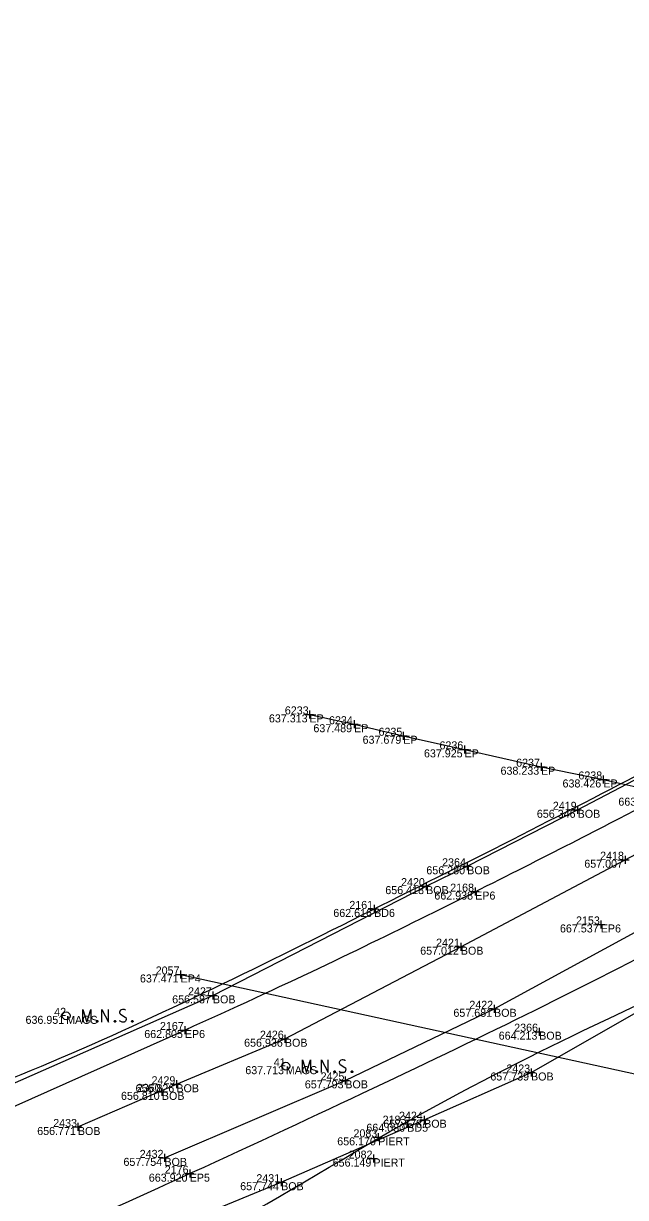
# Model space of a CAD drawing. Extents: x 2197382 to 2204062, y 634117 to 636522.
# Drawn here: x 2202463 to 2202538.2, y 635231.8 to 635378.5 of the extents above; entities that cross this region are included whole.
import ezdxf

# ---------------------------------------------------------------- set-up
doc = ezdxf.new("R2010")
doc.units = 0
for name, color, linetype in [('_CIVIL_CONSTRUCTION', 7, 'Continuous'), ('BR_X_SV_Bottom_of_Beam', 7, 'Continuous'), ('BR_X_SV_Bottom_of_Beam_Text', 7, 'Continuous'), ('BR_X_SV_Deck_Top', 7, 'Continuous'), ('BR_X_SV_Deck_Top_Text', 7, 'Continuous'), ('BR_X_SV_Pier_Cap_Top_Text', 7, 'Continuous'), ('GE_P_Alignment_100_Distances', 7, 'Continuous'), ('SH_Border', 7, 'Continuous'), ('SH_Cut_Line', 7, 'Continuous'), ('SH_Data', 7, 'Continuous'), ('SV_P_Control_Cells_Set', 7, 'Continuous')]:
    doc.layers.add(name, color=color, linetype=linetype)

msp = doc.modelspace()

# ---------------------------------------------------------------- linework, layer by layer
at = {"layer": '_CIVIL_CONSTRUCTION'}
for p, q in [((2202498.24, 635292.2), (2202499.24, 635292.2)), ((2202498.74, 635292.7), (2202498.74, 635291.7)), ((2202498.74, 635292.2), (2202498.74, 635292.2)), ((2202503.82, 635290.97), (2202504.82, 635290.97)), ((2202504.32, 635291.47), (2202504.32, 635290.47)), ((2202504.32, 635290.97), (2202504.32, 635290.97)), ((2202509.96, 635289.53), (2202510.96, 635289.53)), ((2202510.46, 635290.03), (2202510.46, 635289.03)), ((2202510.46, 635289.53), (2202510.46, 635289.53)), ((2202517.62, 635287.83), (2202518.62, 635287.83)), ((2202518.12, 635288.33), (2202518.12, 635287.33)), ((2202518.12, 635287.83), (2202518.12, 635287.83)), ((2202527.18, 635285.66), (2202528.18, 635285.66)), ((2202527.68, 635286.16), (2202527.68, 635285.16)), ((2202527.68, 635285.66), (2202527.68, 635285.66)), ((2202534.97, 635284.07), (2202535.97, 635284.07)), ((2202535.47, 635284.57), (2202535.47, 635283.57)), ((2202535.47, 635284.07), (2202535.47, 635284.07)), ((2202532.26, 635280.78), (2202532.26, 635279.78)), ((2202531.76, 635280.28), (2202532.76, 635280.28)), ((2202532.26, 635280.28), (2202532.26, 635280.28)), ((2202538.19, 635274.54), (2202538.19, 635273.54)), ((2202517.96, 635273.22), (2202518.96, 635273.22)), ((2202518.46, 635273.72), (2202518.46, 635272.72)), ((2202518.46, 635273.22), (2202518.46, 635273.22)), ((2202537.69, 635274.04), (2202538.69, 635274.04)), ((2202538.19, 635274.04), (2202538.19, 635274.04)), ((2202512.82, 635270.74), (2202513.82, 635270.74)), ((2202513.32, 635271.24), (2202513.32, 635270.24)), ((2202513.32, 635270.74), (2202513.32, 635270.74)), ((2202519.45, 635270.55), (2202519.45, 635269.55)), ((2202518.95, 635270.05), (2202519.95, 635270.05)), ((2202519.45, 635270.05), (2202519.45, 635270.05)), ((2202506.32, 635267.89), (2202507.32, 635267.89)), ((2202506.82, 635268.39), (2202506.82, 635267.39)), ((2202506.82, 635267.89), (2202506.82, 635267.89)), ((2202534.65, 635265.95), (2202535.65, 635265.95)), ((2202535.15, 635266.45), (2202535.15, 635265.45)), ((2202535.15, 635265.95), (2202535.15, 635265.95)), ((2202517.16, 635263.17), (2202518.16, 635263.17)), ((2202517.66, 635263.67), (2202517.66, 635262.67)), ((2202517.66, 635263.17), (2202517.66, 635263.17)), ((2202482.63, 635260.2), (2202482.63, 635259.2)), ((2202482.13, 635259.7), (2202483.13, 635259.7)), ((2202482.63, 635259.7), (2202482.63, 635259.7)), ((2202486.17, 635257.09), (2202487.17, 635257.09)), ((2202486.67, 635257.59), (2202486.67, 635256.59)), ((2202486.67, 635257.09), (2202486.67, 635257.09)), ((2202521.81, 635255.91), (2202521.81, 635254.91)), ((2202521.31, 635255.41), (2202522.31, 635255.41)), ((2202521.81, 635255.41), (2202521.81, 635255.41)), ((2202482.66, 635252.76), (2202483.66, 635252.76)), ((2202483.16, 635253.26), (2202483.16, 635252.26)), ((2202483.16, 635252.76), (2202483.16, 635252.76)), ((2202526.95, 635252.55), (2202527.95, 635252.55)), ((2202527.45, 635253.05), (2202527.45, 635252.05)), ((2202527.45, 635252.55), (2202527.45, 635252.55)), ((2202495.17, 635251.67), (2202496.17, 635251.67)), ((2202495.67, 635252.17), (2202495.67, 635251.17)), ((2202495.67, 635251.67), (2202495.67, 635251.67)), ((2202503.22, 635246.97), (2202503.22, 635245.97)), ((2202525.93, 635247.45), (2202526.93, 635247.45)), ((2202526.43, 635247.95), (2202526.43, 635246.95)), ((2202526.43, 635247.45), (2202526.43, 635247.45)), ((2202480.29, 635245.53), (2202480.29, 635244.53)), ((2202481.61, 635245.98), (2202482.61, 635245.98)), ((2202482.11, 635246.48), (2202482.11, 635245.48)), ((2202482.11, 635245.98), (2202482.11, 635245.98)), ((2202502.72, 635246.47), (2202503.72, 635246.47)), ((2202503.22, 635246.47), (2202503.22, 635246.47)), ((2202479.79, 635245.03), (2202480.79, 635245.03)), ((2202480.29, 635245.03), (2202480.29, 635245.03)), ((2202469.79, 635241.14), (2202469.79, 635240.14)), ((2202510.46, 635241.05), (2202511.46, 635241.05)), ((2202510.96, 635241.55), (2202510.96, 635240.55)), ((2202510.96, 635241.05), (2202510.96, 635241.05)), ((2202512.57, 635241.55), (2202513.57, 635241.55)), ((2202513.07, 635242.05), (2202513.07, 635241.05)), ((2202513.07, 635241.55), (2202513.07, 635241.55)), ((2202469.29, 635240.64), (2202470.29, 635240.64)), ((2202469.79, 635240.64), (2202469.79, 635240.64)), ((2202506.83, 635239.35), (2202507.83, 635239.35)), ((2202507.33, 635239.85), (2202507.33, 635238.85)), ((2202507.33, 635239.35), (2202507.33, 635239.35)), ((2202480.11, 635236.78), (2202481.11, 635236.78)), ((2202480.61, 635237.28), (2202480.61, 635236.28)), ((2202480.61, 635236.78), (2202480.61, 635236.78)), ((2202506.23, 635236.69), (2202507.23, 635236.69)), ((2202506.73, 635237.19), (2202506.73, 635236.19)), ((2202506.73, 635236.69), (2202506.73, 635236.69)), ((2202483.77, 635235.31), (2202483.77, 635234.31)), ((2202483.27, 635234.81), (2202484.27, 635234.81)), ((2202483.77, 635234.81), (2202483.77, 635234.81)), ((2202494.7, 635233.74), (2202495.7, 635233.74)), ((2202495.2, 635234.24), (2202495.2, 635233.24)), ((2202495.2, 635233.74), (2202495.2, 635233.74))]:
    msp.add_line(p, q, dxfattribs=at)
at = {"layer": 'BR_X_SV_Bottom_of_Beam'}
msp.add_line((2202471.48, 635223.99), (2202495.2, 635233.74), dxfattribs=at)
for points in [[(2202513.32, 635270.74), (2202518.46, 635273.22), (2202532.26, 635280.28), (2202548.24, 635288.65), (2202560.65, 635295.12), (2202588.28, 635310.4), (2202608.69, 635322.99), (2202620.52, 635330.21), (2202626.07, 635333.71), (2202636.25, 635340.13), (2202656.93, 635353.89), (2202662.46, 635358.97), (2202720.9, 635399.77), (2202735.15, 635410.44), (2202760.7, 635432.08)], [(2202480.61, 635236.78), (2202503.22, 635246.47), (2202521.81, 635255.41), (2202544.65, 635267.81), (2202563.46, 635278.16), (2202584.32, 635289.66), (2202600.02, 635298.57)], [(2202469.79, 635240.64), (2202482.11, 635245.98), (2202495.67, 635251.67), (2202517.66, 635263.17), (2202538.19, 635274.04), (2202552.84, 635281.79), (2202572.87, 635292.54)], [(2202452.05, 635241.83), (2202486.67, 635257.09), (2202513.32, 635270.74)], [(2202495.2, 635233.74), (2202513.07, 635241.55), (2202526.43, 635247.45), (2202550.74, 635261.3)]]:
    msp.add_lwpolyline(points, dxfattribs=at)
at = {"layer": 'BR_X_SV_Deck_Top'}
for points in [[(2202430.05, 635233.59), (2202439.74, 635238.51), (2202466.34, 635247.69), (2202507.17, 635268.03), (2202543.72, 635286.4), (2202574.88, 635303.71), (2202604.91, 635320.16), (2202634.13, 635339.4), (2202663.02, 635358.59), (2202692.44, 635376.51), (2202729.25, 635404.45), (2202755.81, 635426.42), (2202769.74, 635438.84)], [(2202458.05, 635216.68), (2202477.12, 635219.98), (2202511.72, 635243.78), (2202554.96, 635262.3), (2202588.01, 635280.67), (2202608.34, 635292.39), (2202640.83, 635312.14), (2202668.15, 635329.95), (2202698.57, 635351.31), (2202722.13, 635368.65), (2202754.6, 635393.43), (2202777.49, 635412.29), (2202789.61, 635422.64)]]:
    msp.add_open_spline(points, degree=3, dxfattribs=at)
at = {"layer": 'GE_P_Alignment_100_Distances'}
for p, q in [((2202535.15, 635265.95), (2202535.15, 635265.95)), ((2202437.86, 635232.53), (2202483.16, 635252.76))]:
    msp.add_line(p, q, dxfattribs=at)
for points in [[(2202498.74, 635292.2), (2202504.32, 635290.97), (2202510.46, 635289.53), (2202518.12, 635287.83), (2202527.68, 635285.66), (2202535.47, 635284.07), (2202543.69, 635282.23), (2202552.96, 635280.17), (2202564.04, 635277.92), (2202577.1, 635275.33), (2202589.15, 635272.89), (2202599.87, 635270.95), (2202613.44, 635268.28), (2202628.15, 635265.39), (2202641.92, 635262.82), (2202654.4, 635260.66), (2202664.33, 635258.84), (2202676.16, 635256.72), (2202690.38, 635253.86), (2202704.42, 635251.17), (2202718.67, 635248.71), (2202737.35, 635245.36), (2202761.23, 635240.85), (2202781.34, 635237.18)], [(2202482.63, 635259.7), (2202569.32, 635240.74), (2202617.18, 635230.71), (2202631.86, 635227.59), (2202654.83, 635223.14), (2202694.02, 635215.69), (2202726.45, 635210.27), (2202846.08, 635190.3)]]:
    msp.add_lwpolyline(points, dxfattribs=at)
for points in [[(2202483.16, 635252.76), (2202495.4, 635258.23), (2202515.21, 635267.82), (2202539.51, 635280.18), (2202556.27, 635289.07), (2202570.79, 635297.09), (2202585.76, 635305.34), (2202607.83, 635319.01), (2202630.78, 635332.65), (2202656.43, 635348.81), (2202675.69, 635362.47), (2202698.98, 635379.18), (2202729.9, 635401.35), (2202753.67, 635420.87), (2202767.82, 635433.18)], [(2202457.67, 635223.28), (2202466.48, 635226.87), (2202500.46, 635242.35), (2202539.48, 635261.18), (2202573.06, 635279.52), (2202585.61, 635286.63), (2202599.84, 635294.84), (2202617.62, 635305.23), (2202642.29, 635320.4), (2202667.37, 635336.77), (2202691.72, 635353.63), (2202713.41, 635369.4), (2202739.64, 635388.97), (2202758.66, 635404.28), (2202770.06, 635413.81)]]:
    msp.add_open_spline(points, degree=3, dxfattribs=at)
at = {"layer": 'SV_P_Control_Cells_Set'}
for points in [[(2202470.42, 635253.73), (2202470.42, 635255.33), (2202470.92, 635253.73), (2202471.41, 635255.33), (2202471.41, 635253.73)], [(2202472.79, 635253.73), (2202472.79, 635255.33), (2202473.61, 635253.73), (2202473.61, 635255.33)], [(2202475.76, 635255.22), (2202475.74, 635255.24), (2202475.71, 635255.27), (2202475.61, 635255.31), (2202475.49, 635255.33), (2202475.4, 635255.33), (2202475.37, 635255.33), (2202475.22, 635255.29), (2202475.1, 635255.22), (2202475.02, 635255.12), (2202475, 635255.02), (2202475, 635254.94), (2202475.02, 635254.84), (2202475.11, 635254.75), (2202475.72, 635254.37), (2202475.77, 635254.32), (2202475.8, 635254.27), (2202475.82, 635254.2), (2202475.82, 635254.12), (2202475.81, 635254.05), (2202475.8, 635254), (2202475.77, 635253.93), (2202475.75, 635253.88), (2202475.73, 635253.85), (2202475.7, 635253.81), (2202475.66, 635253.78), (2202475.62, 635253.76), (2202475.59, 635253.75), (2202475.49, 635253.73), (2202475.33, 635253.73), (2202475.23, 635253.76), (2202475.09, 635253.85), (2202475, 635253.92)], [(2202472.18, 635253.95), (2202472.24, 635253.95), (2202472.27, 635253.92), (2202472.3, 635253.87), (2202472.3, 635253.81), (2202472.27, 635253.76), (2202472.24, 635253.73), (2202472.18, 635253.73), (2202472.15, 635253.76), (2202472.12, 635253.81), (2202472.12, 635253.87), (2202472.15, 635253.92), (2202472.18, 635253.95)], [(2202474.4, 635253.95), (2202474.45, 635253.95), (2202474.48, 635253.92), (2202474.52, 635253.87), (2202474.52, 635253.81), (2202474.48, 635253.76), (2202474.45, 635253.73), (2202474.4, 635253.73), (2202474.36, 635253.76), (2202474.33, 635253.81), (2202474.33, 635253.87), (2202474.36, 635253.92), (2202474.4, 635253.95)], [(2202476.58, 635253.95), (2202476.63, 635253.95), (2202476.67, 635253.92), (2202476.7, 635253.87), (2202476.7, 635253.81), (2202476.67, 635253.76), (2202476.63, 635253.73), (2202476.58, 635253.73), (2202476.55, 635253.76), (2202476.51, 635253.81), (2202476.51, 635253.87), (2202476.55, 635253.92), (2202476.58, 635253.95)], [(2202497.87, 635247.44), (2202497.87, 635249.04), (2202498.38, 635247.44), (2202498.86, 635249.04), (2202498.86, 635247.44)], [(2202500.24, 635247.44), (2202500.24, 635249.04), (2202501.07, 635247.44), (2202501.07, 635249.04)], [(2202503.22, 635248.92), (2202503.2, 635248.95), (2202503.16, 635248.97), (2202503.06, 635249.01), (2202502.94, 635249.04), (2202502.85, 635249.04), (2202502.82, 635249.04), (2202502.68, 635249), (2202502.56, 635248.92), (2202502.48, 635248.82), (2202502.46, 635248.72), (2202502.46, 635248.65), (2202502.48, 635248.55), (2202502.57, 635248.46), (2202503.17, 635248.08), (2202503.23, 635248.03), (2202503.25, 635247.98), (2202503.27, 635247.9), (2202503.27, 635247.83), (2202503.26, 635247.75), (2202503.25, 635247.7), (2202503.23, 635247.64), (2202503.21, 635247.59), (2202503.19, 635247.55), (2202503.15, 635247.51), (2202503.12, 635247.49), (2202503.08, 635247.46), (2202503.04, 635247.45), (2202502.94, 635247.44), (2202502.79, 635247.44), (2202502.69, 635247.46), (2202502.55, 635247.55), (2202502.46, 635247.63)], [(2202499.64, 635247.65), (2202499.69, 635247.65), (2202499.72, 635247.63), (2202499.76, 635247.58), (2202499.76, 635247.51), (2202499.72, 635247.46), (2202499.69, 635247.44), (2202499.64, 635247.44), (2202499.6, 635247.46), (2202499.57, 635247.51), (2202499.57, 635247.58), (2202499.6, 635247.63), (2202499.64, 635247.65)], [(2202501.85, 635247.65), (2202501.91, 635247.65), (2202501.94, 635247.63), (2202501.97, 635247.58), (2202501.97, 635247.51), (2202501.94, 635247.46), (2202501.91, 635247.44), (2202501.85, 635247.44), (2202501.82, 635247.46), (2202501.79, 635247.51), (2202501.79, 635247.58), (2202501.82, 635247.63), (2202501.85, 635247.65)], [(2202504.03, 635247.65), (2202504.09, 635247.65), (2202504.12, 635247.63), (2202504.16, 635247.58), (2202504.16, 635247.51), (2202504.12, 635247.46), (2202504.09, 635247.44), (2202504.03, 635247.44), (2202504, 635247.46), (2202503.97, 635247.51), (2202503.97, 635247.58), (2202504, 635247.63), (2202504.03, 635247.65)]]:
    msp.add_lwpolyline(points, dxfattribs=at)
for centre in [(2202468.33, 635254.53), (2202495.78, 635248.24)]:
    msp.add_circle(centre, 0.497, dxfattribs=at)

# ---------------------------------------------------------------- texts
at = {"layer": 'BR_X_SV_Bottom_of_Beam_Text'}
for s, p in [('2419', (2202529.16, 635280.28)), ('656.346', (2202527.16, 635279.28)), ('BOB', (2202532.26, 635279.28)), ('2418', (2202535.07, 635274.04)), ('656.280', (2202513.35, 635272.22)), ('2364', (2202515.32, 635273.22)), ('BOB', (2202518.46, 635272.22)), ('657.007', (2202533.09, 635273.04)), ('2420', (2202510.19, 635270.74)), ('656.418', (2202508.22, 635269.74)), ('BOB', (2202513.32, 635269.74)), ('657.012', (2202512.58, 635262.17)), ('2421', (2202514.56, 635263.17)), ('BOB', (2202517.66, 635262.17)), ('656.587', (2202481.58, 635256.09)), ('2427', (2202483.56, 635257.09)), ('BOB', (2202486.67, 635256.09)), ('2422', (2202518.72, 635255.41)), ('657.681', (2202516.73, 635254.41)), ('BOB', (2202521.81, 635254.41)), ('2426', (2202492.55, 635251.67)), ('664.213', (2202522.39, 635251.55)), ('2366', (2202524.33, 635252.55)), ('BOB', (2202527.45, 635251.55)), ('656.936', (2202490.57, 635250.67)), ('BOB', (2202495.67, 635250.67)), ('2423', (2202523.35, 635247.45)), ('2429', (2202479, 635245.98)), ('2425', (2202500.13, 635246.47)), ('657.739', (2202521.35, 635246.45)), ('BOB', (2202526.43, 635246.45)), ('656.826', (2202477, 635244.98)), ('2360', (2202477.16, 635245.03)), ('BOB', (2202482.11, 635244.98)), ('657.793', (2202498.16, 635245.47)), ('BOB', (2202503.22, 635245.47)), ('656.810', (2202475.18, 635244.03)), ('BOB', (2202480.29, 635244.03)), ('2424', (2202509.93, 635241.55)), ('2433', (2202466.71, 635240.64)), ('657.778', (2202507.97, 635240.55)), ('BOB', (2202513.07, 635240.55)), ('656.771', (2202464.71, 635239.64)), ('BOB', (2202469.79, 635239.64)), ('657.754', (2202475.49, 635235.78)), ('2432', (2202477.52, 635236.78)), ('BOB', (2202480.61, 635235.78)), ('657.744', (2202490.08, 635232.74)), ('2431', (2202492.1, 635233.74)), ('BOB', (2202495.2, 635232.74))]:
    msp.add_text(s, height=1, dxfattribs=at).set_placement(p)
at = {"layer": 'BR_X_SV_Deck_Top_Text'}
for s, p in [('2161', (2202503.72, 635267.89)), ('662.616', (2202501.72, 635266.89)), ('BD6', (2202506.82, 635266.89)), ('664.080', (2202505.85, 635240.05)), ('2183', (2202507.88, 635241.05)), ('BD5', (2202510.96, 635240.05))]:
    msp.add_text(s, height=1, dxfattribs=at).set_placement(p)
at = {"layer": 'BR_X_SV_Pier_Cap_Top_Text'}
for s, p in [('656.170', (2202502.21, 635238.35)), ('2083', (2202504.24, 635239.35)), ('PIERT', (2202507.33, 635238.35)), ('656.149', (2202501.64, 635235.69)), ('2082', (2202503.64, 635236.69)), ('PIERT', (2202506.73, 635235.69))]:
    msp.add_text(s, height=1, dxfattribs=at).set_placement(p)
at = {"layer": 'SH_Border'}
for s, p in [('EP', (2202498.74, 635291.2)), ('EP', (2202504.32, 635289.97)), ('EP', (2202510.46, 635288.53)), ('EP', (2202518.12, 635286.83)), ('EP', (2202527.68, 635284.66)), ('EP', (2202535.47, 635283.07)), ('EP6', (2202519.45, 635269.06)), ('EP6', (2202535.15, 635264.95)), ('EP4', (2202482.63, 635258.7)), ('MAGS', (2202468.33, 635253.53)), ('EP6', (2202483.16, 635251.76)), ('MAGS', (2202495.78, 635247.24)), ('EP5', (2202483.77, 635233.81))]:
    msp.add_text(s, height=1, dxfattribs=at).set_placement(p)
at = {"layer": 'SH_Cut_Line'}
for s, p in [('6233', (2202495.66, 635292.2)), ('6234', (2202501.18, 635290.97)), ('6235', (2202507.37, 635289.53)), ('6236', (2202514.99, 635287.83)), ('6237', (2202524.57, 635285.66)), ('6238', (2202532.35, 635284.07)), ('2168', (2202516.33, 635270.05)), ('2153', (2202532.06, 635265.95)), ('2057', (2202479.52, 635259.7)), ('42', (2202466.83, 635254.53)), ('2167', (2202480.05, 635252.76)), ('41', (2202494.28, 635248.24)), ('2176', (2202480.65, 635234.81))]:
    msp.add_text(s, height=1, dxfattribs=at).set_placement(p)
at = {"layer": 'SH_Data'}
for s, p in [('637.313', (2202493.67, 635291.2)), ('637.489', (2202499.23, 635289.97)), ('637.679', (2202505.38, 635288.53)), ('637.925', (2202513.05, 635286.83)), ('638.233', (2202522.62, 635284.66)), ('638.426', (2202530.37, 635283.07)), ('663.056', (2202537.35, 635280.79)), ('662.938', (2202514.35, 635269.06)), ('667.537', (2202530.05, 635264.95)), ('637.471', (2202477.55, 635258.7)), ('636.951', (2202463.25, 635253.53)), ('662.805', (2202478.09, 635251.76)), ('637.713', (2202490.72, 635247.24)), ('663.920', (2202478.66, 635233.81))]:
    msp.add_text(s, height=1, dxfattribs=at).set_placement(p)

doc.saveas('drawing.dxf')
